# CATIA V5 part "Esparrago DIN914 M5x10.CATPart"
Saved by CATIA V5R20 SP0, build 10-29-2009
Part number: Esparrago DIN914 M5x10
Revision: ANY
Definition: UNKNOWN
Nomenclature: Esparrago DIN914 M5x10
Source: Unknown
Bounding box of the stored display mesh (mm): x -2.5 to 2.5, y -2.5 to 2.5, z 0 to 9.5
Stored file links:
  C:\Users\Utente\Desktop\IO LAVORO\3D X SITO CF\X SITO\3D files UM\UM064242 PRODUCT\Esparrago DIN914 M5x10.CATPart
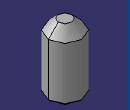
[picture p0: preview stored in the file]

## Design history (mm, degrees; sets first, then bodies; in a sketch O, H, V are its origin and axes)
Body1 "Cortar-Extruir2" (main body)
  Solid1: solid without history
